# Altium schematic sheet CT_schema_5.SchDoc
size 367 x 245 mm
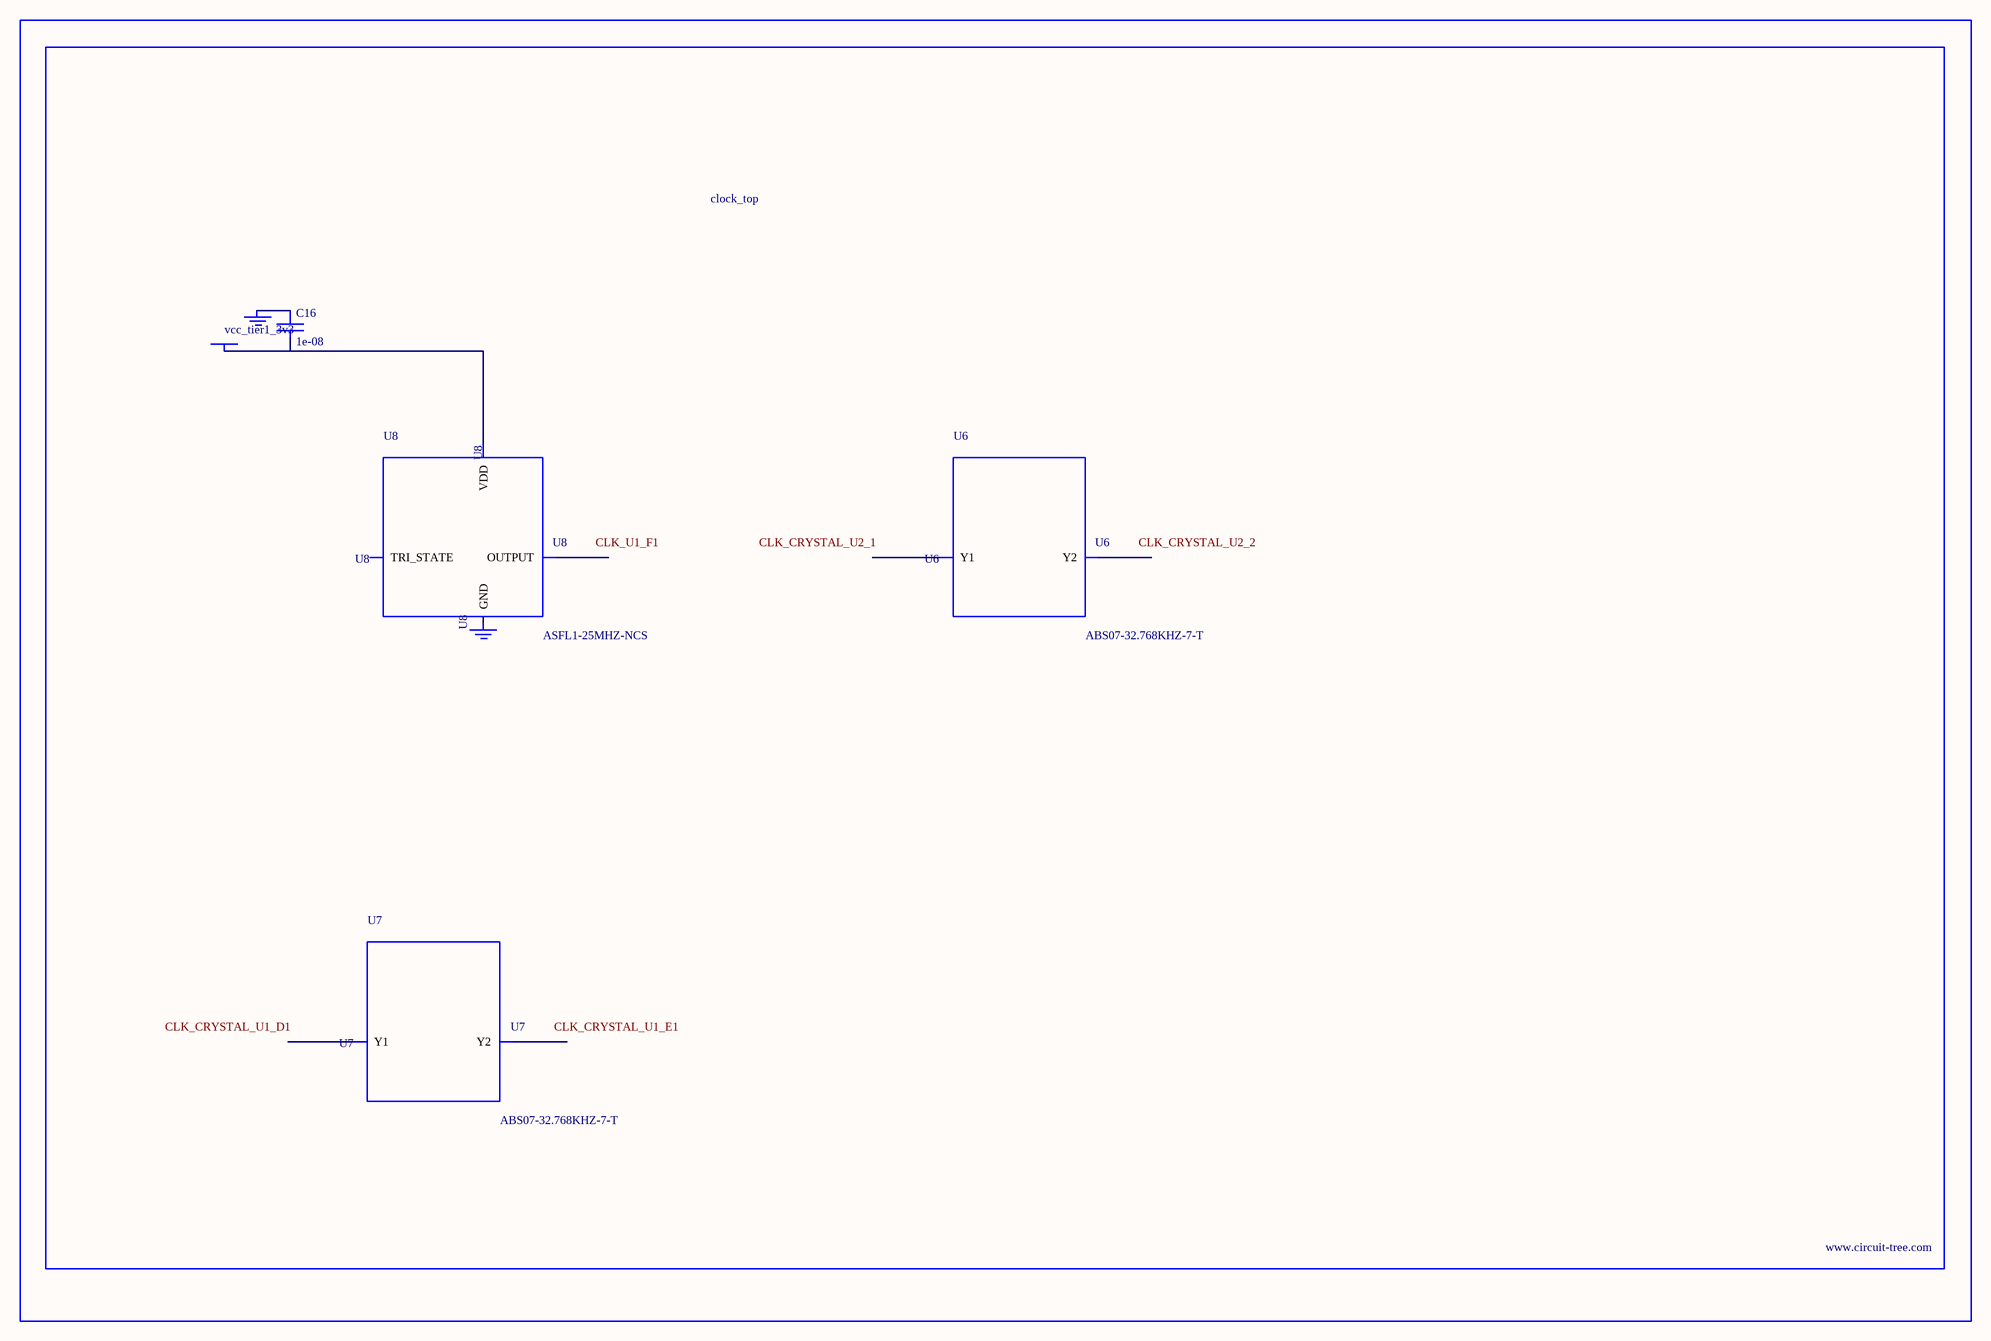
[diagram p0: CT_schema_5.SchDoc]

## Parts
BORDER4  (no value)
C16  1e-08  [C0402]
GND_INSTANCE_4_0  (no value)
GND_INSTANCE_4_1  (no value)
POWER_INSTANCE_4_0  vcc_tier1_3v3
U6  ABS07-32.768KHZ-7-T  [ABS07-32.768KHZ-7-T]
U7  ABS07-32.768KHZ-7-T  [ABS07-32.768KHZ-7-T]
U8  ASFL1-25MHZ-NCS  [ASFL1]

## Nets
NetC16_1: C16.1 GND_INSTANCE_4_0.0(GND)
NetC16_2: C16.2 POWER_INSTANCE_4_0.0(PWR) U8.4(VDD)

Not connected (* = marked no-connect by the designer): GND_INSTANCE_4_1 0(GND); U6 1(Y1) 2(Y2); U7 1(Y1) 2(Y2); U8 1(TRI_STATE) 2(GND) 3(OUTPUT)

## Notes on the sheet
- Labels drawn without touching a wire or pin: CLK_CRYSTAL_U1_D1, CLK_CRYSTAL_U1_E1, CLK_CRYSTAL_U2_1, CLK_CRYSTAL_U2_2, CLK_U1_F1

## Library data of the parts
BORDER4 = BORDER_PAGE4
C16 = C0402C103K3RAC
GND_INSTANCE_4_0 GND_INSTANCE_4_1 = GND
POWER_INSTANCE_4_0 = PWR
